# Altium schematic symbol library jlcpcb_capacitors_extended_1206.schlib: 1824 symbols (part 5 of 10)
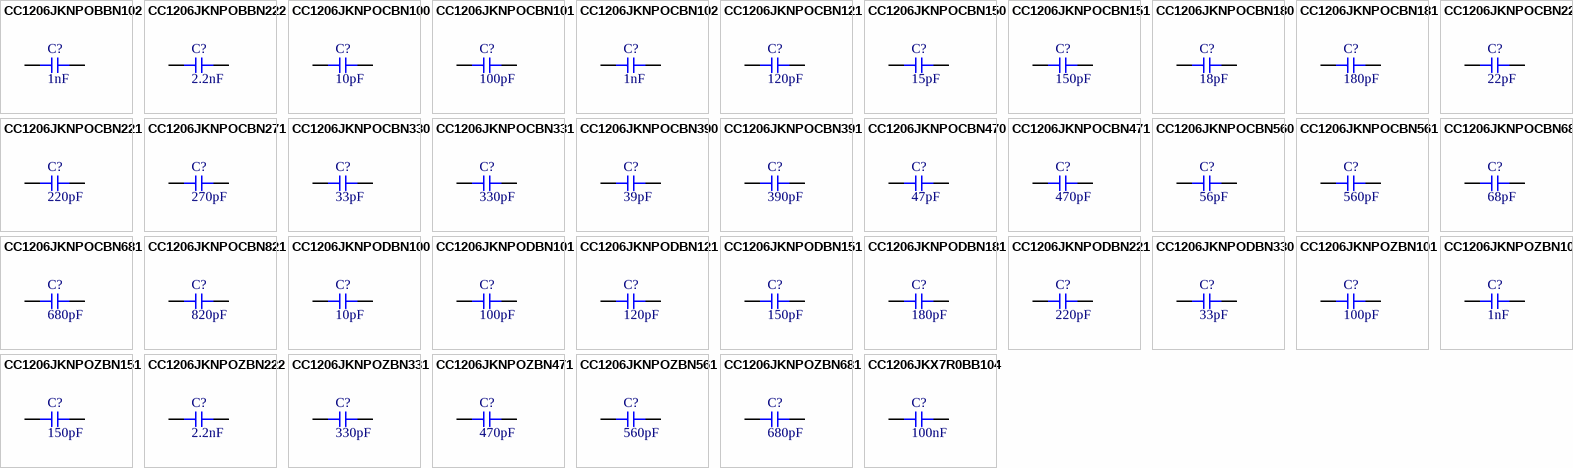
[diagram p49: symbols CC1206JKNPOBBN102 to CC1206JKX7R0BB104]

## CC1206JKNPOBBN102
designator C?  Capacitance: 1nF  (hidden comment: *)
Capacitor, Ceramic (MLCC), 1nF, ±5%, 500V, NP0, ±5%, SMD 1206; Manufacturer: YAGEO; Manufacturer Part Number: CC1206JKNPOBBN102
footprint CAP-1206 (1206 (3216M) Capacitor)
pins: 1, 2

## CC1206JKNPOBBN222
designator C?  Capacitance: 2.2nF  (hidden comment: *)
Capacitor, Ceramic (MLCC), 2.2nF, ±5%, 500V, NP0, ±5%, SMD 1206; Manufacturer: YAGEO; Manufacturer Part Number: CC1206JKNPOBBN222
footprint CAP-1206 (1206 (3216M) Capacitor)
pins: 1, 2

## CC1206JKNPOCBN100
designator C?  Capacitance: 10pF  (hidden comment: *)
Capacitor, Ceramic (MLCC), 10pF, ±5%, 1kV, NP0, ±5%, SMD 1206; Manufacturer: YAGEO; Manufacturer Part Number: CC1206JKNPOCBN100
footprint CAP-1206 (1206 (3216M) Capacitor)
pins: 1, 2

## CC1206JKNPOCBN101
designator C?  Capacitance: 100pF  (hidden comment: *)
Capacitor, Ceramic (MLCC), 100pF, ±5%, 1kV, NP0, ±5%, SMD 1206; Manufacturer: YAGEO; Manufacturer Part Number: CC1206JKNPOCBN101
footprint CAP-1206 (1206 (3216M) Capacitor)
pins: 1, 2

## CC1206JKNPOCBN102
designator C?  Capacitance: 1nF  (hidden comment: *)
Capacitor, Ceramic (MLCC), 1nF, ±5%, 1kV, NP0, ±5%, SMD 1206; Manufacturer: YAGEO; Manufacturer Part Number: CC1206JKNPOCBN102
footprint CAP-1206 (1206 (3216M) Capacitor)
pins: 1, 2

## CC1206JKNPOCBN121
designator C?  Capacitance: 120pF  (hidden comment: *)
Capacitor, Ceramic (MLCC), 120pF, ±5%, 1kV, NP0, ±5%, SMD 1206; Manufacturer: YAGEO; Manufacturer Part Number: CC1206JKNPOCBN121
footprint CAP-1206 (1206 (3216M) Capacitor)
pins: 1, 2

## CC1206JKNPOCBN150
designator C?  Capacitance: 15pF  (hidden comment: *)
Capacitor, Ceramic (MLCC), 15pF, ±5%, 1kV, NP0, ±5%, SMD 1206; Manufacturer: YAGEO; Manufacturer Part Number: CC1206JKNPOCBN150
footprint CAP-1206 (1206 (3216M) Capacitor)
pins: 1, 2

## CC1206JKNPOCBN151
designator C?  Capacitance: 150pF  (hidden comment: *)
Capacitor, Ceramic (MLCC), 150pF, ±5%, 1kV, NP0, ±5%, SMD 1206; Manufacturer: YAGEO; Manufacturer Part Number: CC1206JKNPOCBN151
footprint CAP-1206 (1206 (3216M) Capacitor)
pins: 1, 2

## CC1206JKNPOCBN180
designator C?  Capacitance: 18pF  (hidden comment: *)
Capacitor, Ceramic (MLCC), 18pF, ±5%, 1kV, NP0, ±5%, SMD 1206; Manufacturer: YAGEO; Manufacturer Part Number: CC1206JKNPOCBN180
footprint CAP-1206 (1206 (3216M) Capacitor)
pins: 1, 2

## CC1206JKNPOCBN181
designator C?  Capacitance: 180pF  (hidden comment: *)
Capacitor, Ceramic (MLCC), 180pF, ±5%, 1kV, NP0, ±5%, SMD 1206; Manufacturer: YAGEO; Manufacturer Part Number: CC1206JKNPOCBN181
footprint CAP-1206 (1206 (3216M) Capacitor)
pins: 1, 2

## CC1206JKNPOCBN220
designator C?  Capacitance: 22pF  (hidden comment: *)
Capacitor, Ceramic (MLCC), 22pF, ±5%, 1kV, NP0, ±5%, SMD 1206; Manufacturer: YAGEO; Manufacturer Part Number: CC1206JKNPOCBN220
footprint CAP-1206 (1206 (3216M) Capacitor)
pins: 1, 2

## CC1206JKNPOCBN221
designator C?  Capacitance: 220pF  (hidden comment: *)
Capacitor, Ceramic (MLCC), 220pF, ±5%, 1kV, NP0, ±5%, SMD 1206; Manufacturer: YAGEO; Manufacturer Part Number: CC1206JKNPOCBN221
footprint CAP-1206 (1206 (3216M) Capacitor)
pins: 1, 2

## CC1206JKNPOCBN271
designator C?  Capacitance: 270pF  (hidden comment: *)
Capacitor, Ceramic (MLCC), 270pF, ±5%, 1kV, NP0, ±5%, SMD 1206; Manufacturer: YAGEO; Manufacturer Part Number: CC1206JKNPOCBN271
footprint CAP-1206 (1206 (3216M) Capacitor)
pins: 1, 2

## CC1206JKNPOCBN330
designator C?  Capacitance: 33pF  (hidden comment: *)
Capacitor, Ceramic (MLCC), 33pF, ±5%, 1kV, NP0, ±5%, SMD 1206; Manufacturer: YAGEO; Manufacturer Part Number: CC1206JKNPOCBN330
footprint CAP-1206 (1206 (3216M) Capacitor)
pins: 1, 2

## CC1206JKNPOCBN331
designator C?  Capacitance: 330pF  (hidden comment: *)
Capacitor, Ceramic (MLCC), 330pF, ±5%, 1kV, NP0, ±5%, SMD 1206; Manufacturer: YAGEO; Manufacturer Part Number: CC1206JKNPOCBN331
footprint CAP-1206 (1206 (3216M) Capacitor)
pins: 1, 2

## CC1206JKNPOCBN390
designator C?  Capacitance: 39pF  (hidden comment: *)
Capacitor, Ceramic (MLCC), 39pF, ±5%, 1kV, NP0, ±5%, SMD 1206; Manufacturer: YAGEO; Manufacturer Part Number: CC1206JKNPOCBN390
footprint CAP-1206 (1206 (3216M) Capacitor)
pins: 1, 2

## CC1206JKNPOCBN391
designator C?  Capacitance: 390pF  (hidden comment: *)
Capacitor, Ceramic (MLCC), 390pF, ±5%, 1kV, NP0, ±5%, SMD 1206; Manufacturer: YAGEO; Manufacturer Part Number: CC1206JKNPOCBN391
footprint CAP-1206 (1206 (3216M) Capacitor)
pins: 1, 2

## CC1206JKNPOCBN470
designator C?  Capacitance: 47pF  (hidden comment: *)
Capacitor, Ceramic (MLCC), 47pF, ±5%, 1kV, NP0, ±5%, SMD 1206; Manufacturer: YAGEO; Manufacturer Part Number: CC1206JKNPOCBN470
footprint CAP-1206 (1206 (3216M) Capacitor)
pins: 1, 2

## CC1206JKNPOCBN471
designator C?  Capacitance: 470pF  (hidden comment: *)
Capacitor, Ceramic (MLCC), 470pF, ±5%, 1kV, NP0, ±5%, SMD 1206; Manufacturer: YAGEO; Manufacturer Part Number: CC1206JKNPOCBN471
footprint CAP-1206 (1206 (3216M) Capacitor)
pins: 1, 2

## CC1206JKNPOCBN560
designator C?  Capacitance: 56pF  (hidden comment: *)
Capacitor, Ceramic (MLCC), 56pF, ±5%, 1kV, NP0, ±5%, SMD 1206; Manufacturer: YAGEO; Manufacturer Part Number: CC1206JKNPOCBN560
footprint CAP-1206 (1206 (3216M) Capacitor)
pins: 1, 2

## CC1206JKNPOCBN561
designator C?  Capacitance: 560pF  (hidden comment: *)
Capacitor, Ceramic (MLCC), 560pF, ±5%, 1kV, NP0, ±5%, SMD 1206; Manufacturer: YAGEO; Manufacturer Part Number: CC1206JKNPOCBN561
footprint CAP-1206 (1206 (3216M) Capacitor)
pins: 1, 2

## CC1206JKNPOCBN680
designator C?  Capacitance: 68pF  (hidden comment: *)
Capacitor, Ceramic (MLCC), 68pF, ±5%, 1kV, NP0, ±5%, SMD 1206; Manufacturer: YAGEO; Manufacturer Part Number: CC1206JKNPOCBN680
footprint CAP-1206 (1206 (3216M) Capacitor)
pins: 1, 2

## CC1206JKNPOCBN681
designator C?  Capacitance: 680pF  (hidden comment: *)
Capacitor, Ceramic (MLCC), 680pF, ±5%, 1kV, NP0, ±5%, SMD 1206; Manufacturer: YAGEO; Manufacturer Part Number: CC1206JKNPOCBN681
footprint CAP-1206 (1206 (3216M) Capacitor)
pins: 1, 2

## CC1206JKNPOCBN821
designator C?  Capacitance: 820pF  (hidden comment: *)
Capacitor, Ceramic (MLCC), 820pF, ±5%, 1kV, NP0, ±5%, SMD 1206; Manufacturer: YAGEO; Manufacturer Part Number: CC1206JKNPOCBN821
footprint CAP-1206 (1206 (3216M) Capacitor)
pins: 1, 2

## CC1206JKNPODBN100
designator C?  Capacitance: 10pF  (hidden comment: *)
Capacitor, Ceramic (MLCC), 10pF, ±5%, 2kV, NP0, ±5%, SMD 1206; Manufacturer: YAGEO; Manufacturer Part Number: CC1206JKNPODBN100
footprint CAP-1206 (1206 (3216M) Capacitor)
pins: 1, 2

## CC1206JKNPODBN101
designator C?  Capacitance: 100pF  (hidden comment: *)
Capacitor, Ceramic (MLCC), 100pF, ±5%, 2kV, NP0, ±5%, SMD 1206; Manufacturer: YAGEO; Manufacturer Part Number: CC1206JKNPODBN101
footprint CAP-1206 (1206 (3216M) Capacitor)
pins: 1, 2

## CC1206JKNPODBN121
designator C?  Capacitance: 120pF  (hidden comment: *)
Capacitor, Ceramic (MLCC), 120pF, ±5%, 2kV, NP0, ±5%, SMD 1206; Manufacturer: YAGEO; Manufacturer Part Number: CC1206JKNPODBN121
footprint CAP-1206 (1206 (3216M) Capacitor)
pins: 1, 2

## CC1206JKNPODBN151
designator C?  Capacitance: 150pF  (hidden comment: *)
Capacitor, Ceramic (MLCC), 150pF, ±5%, 2kV, NP0, ±5%, SMD 1206; Manufacturer: YAGEO; Manufacturer Part Number: CC1206JKNPODBN151
footprint CAP-1206 (1206 (3216M) Capacitor)
pins: 1, 2

## CC1206JKNPODBN181
designator C?  Capacitance: 180pF  (hidden comment: *)
Capacitor, Ceramic (MLCC), 180pF, ±5%, 2kV, NP0, ±5%, SMD 1206; Manufacturer: YAGEO; Manufacturer Part Number: CC1206JKNPODBN181
footprint CAP-1206 (1206 (3216M) Capacitor)
pins: 1, 2

## CC1206JKNPODBN221
designator C?  Capacitance: 220pF  (hidden comment: *)
Capacitor, Ceramic (MLCC), 220pF, ±5%, 2kV, NP0, ±5%, SMD 1206; Manufacturer: YAGEO; Manufacturer Part Number: CC1206JKNPODBN221
footprint CAP-1206 (1206 (3216M) Capacitor)
pins: 1, 2

## CC1206JKNPODBN330
designator C?  Capacitance: 33pF  (hidden comment: *)
Capacitor, Ceramic (MLCC), 33pF, ±5%, 2kV, NP0, ±5%, SMD 1206; Manufacturer: YAGEO; Manufacturer Part Number: CC1206JKNPODBN330
footprint CAP-1206 (1206 (3216M) Capacitor)
pins: 1, 2

## CC1206JKNPOZBN101
designator C?  Capacitance: 100pF  (hidden comment: *)
Capacitor, Ceramic (MLCC), 100pF, ±5%, 630V, NP0, ±5%, SMD 1206; Manufacturer: YAGEO; Manufacturer Part Number: CC1206JKNPOZBN101
footprint CAP-1206 (1206 (3216M) Capacitor)
pins: 1, 2

## CC1206JKNPOZBN102
designator C?  Capacitance: 1nF  (hidden comment: *)
Capacitor, Ceramic (MLCC), 1nF, ±5%, 630V, NP0, ±5%, SMD 1206; Manufacturer: YAGEO; Manufacturer Part Number: CC1206JKNPOZBN102
footprint CAP-1206 (1206 (3216M) Capacitor)
pins: 1, 2

## CC1206JKNPOZBN151
designator C?  Capacitance: 150pF  (hidden comment: *)
Capacitor, Ceramic (MLCC), 150pF, ±5%, 630V, NP0, ±5%, SMD 1206; Manufacturer: YAGEO; Manufacturer Part Number: CC1206JKNPOZBN151
footprint CAP-1206 (1206 (3216M) Capacitor)
pins: 1, 2

## CC1206JKNPOZBN222
designator C?  Capacitance: 2.2nF  (hidden comment: *)
Capacitor, Ceramic (MLCC), 2.2nF, ±5%, 630V, NP0, ±5%, SMD 1206; Manufacturer: YAGEO; Manufacturer Part Number: CC1206JKNPOZBN222
footprint CAP-1206 (1206 (3216M) Capacitor)
pins: 1, 2

## CC1206JKNPOZBN331
designator C?  Capacitance: 330pF  (hidden comment: *)
Capacitor, Ceramic (MLCC), 330pF, ±5%, 630V, NP0, ±5%, SMD 1206; Manufacturer: YAGEO; Manufacturer Part Number: CC1206JKNPOZBN331
footprint CAP-1206 (1206 (3216M) Capacitor)
pins: 1, 2

## CC1206JKNPOZBN471
designator C?  Capacitance: 470pF  (hidden comment: *)
Capacitor, Ceramic (MLCC), 470pF, ±5%, 630V, NP0, ±5%, SMD 1206; Manufacturer: YAGEO; Manufacturer Part Number: CC1206JKNPOZBN471
footprint CAP-1206 (1206 (3216M) Capacitor)
pins: 1, 2

## CC1206JKNPOZBN561
designator C?  Capacitance: 560pF  (hidden comment: *)
Capacitor, Ceramic (MLCC), 560pF, ±5%, 630V, NP0, ±5%, SMD 1206; Manufacturer: YAGEO; Manufacturer Part Number: CC1206JKNPOZBN561
footprint CAP-1206 (1206 (3216M) Capacitor)
pins: 1, 2

## CC1206JKNPOZBN681
designator C?  Capacitance: 680pF  (hidden comment: *)
Capacitor, Ceramic (MLCC), 680pF, ±5%, 630V, NP0, ±5%, SMD 1206; Manufacturer: YAGEO; Manufacturer Part Number: CC1206JKNPOZBN681
footprint CAP-1206 (1206 (3216M) Capacitor)
pins: 1, 2

## CC1206JKX7R0BB104
designator C?  Capacitance: 100nF  (hidden comment: *)
Capacitor, Ceramic (MLCC), 100nF, ±5%, 100V, X7R, ±5%, SMD 1206; Manufacturer: YAGEO; Manufacturer Part Number: CC1206JKX7R0BB104
footprint CAP-1206 (1206 (3216M) Capacitor)
pins: 1, 2

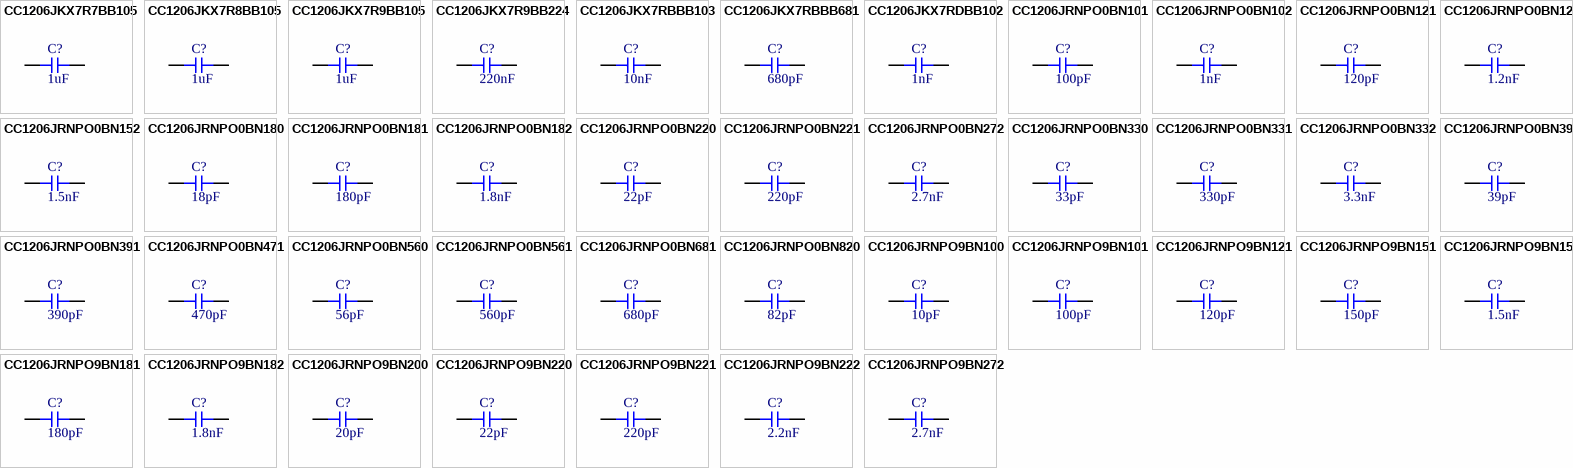
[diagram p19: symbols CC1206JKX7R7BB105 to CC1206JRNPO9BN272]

## CC1206JKX7R7BB105
designator C?  Capacitance: 1uF  (hidden comment: *)
Capacitor, Ceramic (MLCC), 1uF, ±5%, 16V, X7R, ±5%, SMD 1206; Manufacturer: YAGEO; Manufacturer Part Number: CC1206JKX7R7BB105
footprint CAP-1206 (1206 (3216M) Capacitor)
pins: 1, 2

## CC1206JKX7R8BB105
designator C?  Capacitance: 1uF  (hidden comment: *)
Capacitor, Ceramic (MLCC), 1uF, ±5%, 25V, X7R, ±5%, SMD 1206; Manufacturer: YAGEO; Manufacturer Part Number: CC1206JKX7R8BB105
footprint CAP-1206 (1206 (3216M) Capacitor)
pins: 1, 2

## CC1206JKX7R9BB105
designator C?  Capacitance: 1uF  (hidden comment: *)
Capacitor, Ceramic (MLCC), 1uF, ±5%, 50V, X7R, ±5%, SMD 1206; Manufacturer: YAGEO; Manufacturer Part Number: CC1206JKX7R9BB105
footprint CAP-1206 (1206 (3216M) Capacitor)
pins: 1, 2

## CC1206JKX7R9BB224
designator C?  Capacitance: 220nF  (hidden comment: *)
Capacitor, Ceramic (MLCC), 220nF, ±5%, 50V, X7R, ±5%, SMD 1206; Manufacturer: YAGEO; Manufacturer Part Number: CC1206JKX7R9BB224
footprint CAP-1206 (1206 (3216M) Capacitor)
pins: 1, 2

## CC1206JKX7RBBB103
designator C?  Capacitance: 10nF  (hidden comment: *)
Capacitor, Ceramic (MLCC), 10nF, ±5%, 500V, X7R, ±5%, SMD 1206; Manufacturer: YAGEO; Manufacturer Part Number: CC1206JKX7RBBB103
footprint CAP-1206 (1206 (3216M) Capacitor)
pins: 1, 2

## CC1206JKX7RBBB681
designator C?  Capacitance: 680pF  (hidden comment: *)
Capacitor, Ceramic (MLCC), 680pF, ±5%, 500V, X7R, ±5%, SMD 1206; Manufacturer: YAGEO; Manufacturer Part Number: CC1206JKX7RBBB681
footprint CAP-1206 (1206 (3216M) Capacitor)
pins: 1, 2

## CC1206JKX7RDBB102
designator C?  Capacitance: 1nF  (hidden comment: *)
Capacitor, Ceramic (MLCC), 1nF, ±5%, 2kV, X7R, ±5%, SMD 1206; Manufacturer: YAGEO; Manufacturer Part Number: CC1206JKX7RDBB102
footprint CAP-1206 (1206 (3216M) Capacitor)
pins: 1, 2

## CC1206JRNPO0BN101
designator C?  Capacitance: 100pF  (hidden comment: *)
Capacitor, Ceramic (MLCC), 100pF, ±5%, 100V, NP0, ±5%, SMD 1206; Manufacturer: YAGEO; Manufacturer Part Number: CC1206JRNPO0BN101
footprint CAP-1206 (1206 (3216M) Capacitor)
pins: 1, 2

## CC1206JRNPO0BN102
designator C?  Capacitance: 1nF  (hidden comment: *)
Capacitor, Ceramic (MLCC), 1nF, ±5%, 100V, NP0, ±5%, SMD 1206; Manufacturer: YAGEO; Manufacturer Part Number: CC1206JRNPO0BN102
footprint CAP-1206 (1206 (3216M) Capacitor)
pins: 1, 2

## CC1206JRNPO0BN121
designator C?  Capacitance: 120pF  (hidden comment: *)
Capacitor, Ceramic (MLCC), 120pF, ±5%, 100V, NP0, ±5%, SMD 1206; Manufacturer: YAGEO; Manufacturer Part Number: CC1206JRNPO0BN121
footprint CAP-1206 (1206 (3216M) Capacitor)
pins: 1, 2

## CC1206JRNPO0BN122
designator C?  Capacitance: 1.2nF  (hidden comment: *)
Capacitor, Ceramic (MLCC), 1.2nF, ±5%, 100V, NP0, ±5%, SMD 1206; Manufacturer: YAGEO; Manufacturer Part Number: CC1206JRNPO0BN122
footprint CAP-1206 (1206 (3216M) Capacitor)
pins: 1, 2

## CC1206JRNPO0BN152
designator C?  Capacitance: 1.5nF  (hidden comment: *)
Capacitor, Ceramic (MLCC), 1.5nF, ±5%, 100V, NP0, ±5%, SMD 1206; Manufacturer: YAGEO; Manufacturer Part Number: CC1206JRNPO0BN152
footprint CAP-1206 (1206 (3216M) Capacitor)
pins: 1, 2

## CC1206JRNPO0BN180
designator C?  Capacitance: 18pF  (hidden comment: *)
Capacitor, Ceramic (MLCC), 18pF, ±5%, 100V, NP0, ±5%, SMD 1206; Manufacturer: YAGEO; Manufacturer Part Number: CC1206JRNPO0BN180
footprint CAP-1206 (1206 (3216M) Capacitor)
pins: 1, 2

## CC1206JRNPO0BN181
designator C?  Capacitance: 180pF  (hidden comment: *)
Capacitor, Ceramic (MLCC), 180pF, ±5%, 100V, NP0, ±5%, SMD 1206; Manufacturer: YAGEO; Manufacturer Part Number: CC1206JRNPO0BN181
footprint CAP-1206 (1206 (3216M) Capacitor)
pins: 1, 2

## CC1206JRNPO0BN182
designator C?  Capacitance: 1.8nF  (hidden comment: *)
Capacitor, Ceramic (MLCC), 1.8nF, ±5%, 100V, NP0, ±5%, SMD 1206; Manufacturer: YAGEO; Manufacturer Part Number: CC1206JRNPO0BN182
footprint CAP-1206 (1206 (3216M) Capacitor)
pins: 1, 2

## CC1206JRNPO0BN220
designator C?  Capacitance: 22pF  (hidden comment: *)
Capacitor, Ceramic (MLCC), 22pF, ±5%, 100V, NP0, ±5%, SMD 1206; Manufacturer: YAGEO; Manufacturer Part Number: CC1206JRNPO0BN220
footprint CAP-1206 (1206 (3216M) Capacitor)
pins: 1, 2

## CC1206JRNPO0BN221
designator C?  Capacitance: 220pF  (hidden comment: *)
Capacitor, Ceramic (MLCC), 220pF, ±5%, 100V, NP0, ±5%, SMD 1206; Manufacturer: YAGEO; Manufacturer Part Number: CC1206JRNPO0BN221
footprint CAP-1206 (1206 (3216M) Capacitor)
pins: 1, 2

## CC1206JRNPO0BN272
designator C?  Capacitance: 2.7nF  (hidden comment: *)
Capacitor, Ceramic (MLCC), 2.7nF, ±5%, 100V, NP0, ±5%, SMD 1206; Manufacturer: YAGEO; Manufacturer Part Number: CC1206JRNPO0BN272
footprint CAP-1206 (1206 (3216M) Capacitor)
pins: 1, 2

## CC1206JRNPO0BN330
designator C?  Capacitance: 33pF  (hidden comment: *)
Capacitor, Ceramic (MLCC), 33pF, ±5%, 100V, NP0, ±5%, SMD 1206; Manufacturer: YAGEO; Manufacturer Part Number: CC1206JRNPO0BN330
footprint CAP-1206 (1206 (3216M) Capacitor)
pins: 1, 2

## CC1206JRNPO0BN331
designator C?  Capacitance: 330pF  (hidden comment: *)
Capacitor, Ceramic (MLCC), 330pF, ±5%, 100V, NP0, ±5%, SMD 1206; Manufacturer: YAGEO; Manufacturer Part Number: CC1206JRNPO0BN331
footprint CAP-1206 (1206 (3216M) Capacitor)
pins: 1, 2

## CC1206JRNPO0BN332
designator C?  Capacitance: 3.3nF  (hidden comment: *)
Capacitor, Ceramic (MLCC), 3.3nF, ±5%, 100V, NP0, ±5%, SMD 1206; Manufacturer: YAGEO; Manufacturer Part Number: CC1206JRNPO0BN332
footprint CAP-1206 (1206 (3216M) Capacitor)
pins: 1, 2

## CC1206JRNPO0BN390
designator C?  Capacitance: 39pF  (hidden comment: *)
Capacitor, Ceramic (MLCC), 39pF, ±5%, 100V, NP0, ±5%, SMD 1206; Manufacturer: YAGEO; Manufacturer Part Number: CC1206JRNPO0BN390
footprint CAP-1206 (1206 (3216M) Capacitor)
pins: 1, 2

## CC1206JRNPO0BN391
designator C?  Capacitance: 390pF  (hidden comment: *)
Capacitor, Ceramic (MLCC), 390pF, ±5%, 100V, NP0, ±5%, SMD 1206; Manufacturer: YAGEO; Manufacturer Part Number: CC1206JRNPO0BN391
footprint CAP-1206 (1206 (3216M) Capacitor)
pins: 1, 2

## CC1206JRNPO0BN471
designator C?  Capacitance: 470pF  (hidden comment: *)
Capacitor, Ceramic (MLCC), 470pF, ±5%, 100V, NP0, ±5%, SMD 1206; Manufacturer: YAGEO; Manufacturer Part Number: CC1206JRNPO0BN471
footprint CAP-1206 (1206 (3216M) Capacitor)
pins: 1, 2

## CC1206JRNPO0BN560
designator C?  Capacitance: 56pF  (hidden comment: *)
Capacitor, Ceramic (MLCC), 56pF, ±5%, 100V, NP0, ±5%, SMD 1206; Manufacturer: YAGEO; Manufacturer Part Number: CC1206JRNPO0BN560
footprint CAP-1206 (1206 (3216M) Capacitor)
pins: 1, 2

## CC1206JRNPO0BN561
designator C?  Capacitance: 560pF  (hidden comment: *)
Capacitor, Ceramic (MLCC), 560pF, ±5%, 100V, NP0, ±5%, SMD 1206; Manufacturer: YAGEO; Manufacturer Part Number: CC1206JRNPO0BN561
footprint CAP-1206 (1206 (3216M) Capacitor)
pins: 1, 2

## CC1206JRNPO0BN681
designator C?  Capacitance: 680pF  (hidden comment: *)
Capacitor, Ceramic (MLCC), 680pF, ±5%, 100V, NP0, ±5%, SMD 1206; Manufacturer: YAGEO; Manufacturer Part Number: CC1206JRNPO0BN681
footprint CAP-1206 (1206 (3216M) Capacitor)
pins: 1, 2

## CC1206JRNPO0BN820
designator C?  Capacitance: 82pF  (hidden comment: *)
Capacitor, Ceramic (MLCC), 82pF, ±5%, 100V, NP0, ±5%, SMD 1206; Manufacturer: YAGEO; Manufacturer Part Number: CC1206JRNPO0BN820
footprint CAP-1206 (1206 (3216M) Capacitor)
pins: 1, 2

## CC1206JRNPO9BN100
designator C?  Capacitance: 10pF  (hidden comment: *)
Capacitor, Ceramic (MLCC), 10pF, ±5%, 50V, NP0, ±5%, SMD 1206; Manufacturer: YAGEO; Manufacturer Part Number: CC1206JRNPO9BN100
footprint CAP-1206 (1206 (3216M) Capacitor)
pins: 1, 2

## CC1206JRNPO9BN101
designator C?  Capacitance: 100pF  (hidden comment: *)
Capacitor, Ceramic (MLCC), 100pF, ±5%, 50V, NP0, ±5%, SMD 1206; Manufacturer: YAGEO; Manufacturer Part Number: CC1206JRNPO9BN101
footprint CAP-1206 (1206 (3216M) Capacitor)
pins: 1, 2

## CC1206JRNPO9BN121
designator C?  Capacitance: 120pF  (hidden comment: *)
Capacitor, Ceramic (MLCC), 120pF, ±5%, 50V, NP0, ±5%, SMD 1206; Manufacturer: YAGEO; Manufacturer Part Number: CC1206JRNPO9BN121
footprint CAP-1206 (1206 (3216M) Capacitor)
pins: 1, 2

## CC1206JRNPO9BN151
designator C?  Capacitance: 150pF  (hidden comment: *)
Capacitor, Ceramic (MLCC), 150pF, ±5%, 50V, NP0, ±5%, SMD 1206; Manufacturer: YAGEO; Manufacturer Part Number: CC1206JRNPO9BN151
footprint CAP-1206 (1206 (3216M) Capacitor)
pins: 1, 2

## CC1206JRNPO9BN152
designator C?  Capacitance: 1.5nF  (hidden comment: *)
Capacitor, Ceramic (MLCC), 1.5nF, ±5%, 50V, NP0, ±5%, SMD 1206; Manufacturer: YAGEO; Manufacturer Part Number: CC1206JRNPO9BN152
footprint CAP-1206 (1206 (3216M) Capacitor)
pins: 1, 2

## CC1206JRNPO9BN181
designator C?  Capacitance: 180pF  (hidden comment: *)
Capacitor, Ceramic (MLCC), 180pF, ±5%, 50V, NP0, ±5%, SMD 1206; Manufacturer: YAGEO; Manufacturer Part Number: CC1206JRNPO9BN181
footprint CAP-1206 (1206 (3216M) Capacitor)
pins: 1, 2

## CC1206JRNPO9BN182
designator C?  Capacitance: 1.8nF  (hidden comment: *)
Capacitor, Ceramic (MLCC), 1.8nF, ±5%, 50V, NP0, ±5%, SMD 1206; Manufacturer: YAGEO; Manufacturer Part Number: CC1206JRNPO9BN182
footprint CAP-1206 (1206 (3216M) Capacitor)
pins: 1, 2

## CC1206JRNPO9BN200
designator C?  Capacitance: 20pF  (hidden comment: *)
Capacitor, Ceramic (MLCC), 20pF, ±5%, 50V, NP0, ±5%, SMD 1206; Manufacturer: YAGEO; Manufacturer Part Number: CC1206JRNPO9BN200
footprint CAP-1206 (1206 (3216M) Capacitor)
pins: 1, 2

## CC1206JRNPO9BN220
designator C?  Capacitance: 22pF  (hidden comment: *)
Capacitor, Ceramic (MLCC), 22pF, ±5%, 50V, NP0, ±5%, SMD 1206; Manufacturer: YAGEO; Manufacturer Part Number: CC1206JRNPO9BN220
footprint CAP-1206 (1206 (3216M) Capacitor)
pins: 1, 2

## CC1206JRNPO9BN221
designator C?  Capacitance: 220pF  (hidden comment: *)
Capacitor, Ceramic (MLCC), 220pF, ±5%, 50V, NP0, ±5%, SMD 1206; Manufacturer: YAGEO; Manufacturer Part Number: CC1206JRNPO9BN221
footprint CAP-1206 (1206 (3216M) Capacitor)
pins: 1, 2

## CC1206JRNPO9BN222
designator C?  Capacitance: 2.2nF  (hidden comment: *)
Capacitor, Ceramic (MLCC), 2.2nF, ±5%, 50V, NP0, ±5%, SMD 1206; Manufacturer: YAGEO; Manufacturer Part Number: CC1206JRNPO9BN222
footprint CAP-1206 (1206 (3216M) Capacitor)
pins: 1, 2

## CC1206JRNPO9BN272
designator C?  Capacitance: 2.7nF  (hidden comment: *)
Capacitor, Ceramic (MLCC), 2.7nF, ±5%, 50V, NP0, ±5%, SMD 1206; Manufacturer: YAGEO; Manufacturer Part Number: CC1206JRNPO9BN272
footprint CAP-1206 (1206 (3216M) Capacitor)
pins: 1, 2

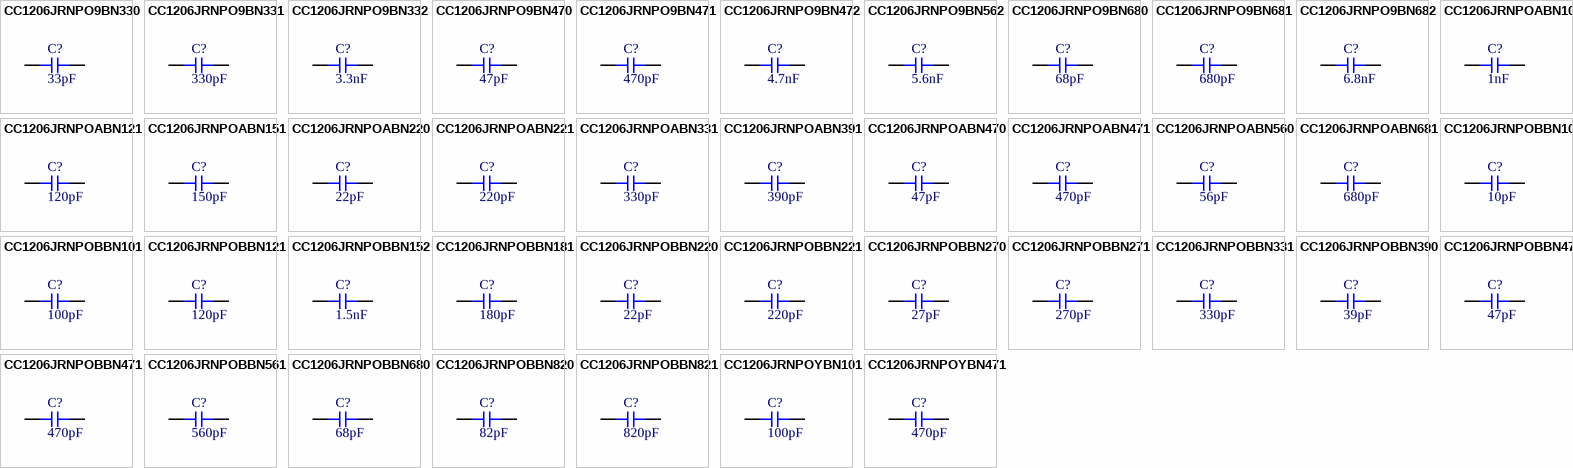
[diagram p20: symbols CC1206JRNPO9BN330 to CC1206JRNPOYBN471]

## CC1206JRNPO9BN330
designator C?  Capacitance: 33pF  (hidden comment: *)
Capacitor, Ceramic (MLCC), 33pF, ±5%, 50V, NP0, ±5%, SMD 1206; Manufacturer: YAGEO; Manufacturer Part Number: CC1206JRNPO9BN330
footprint CAP-1206 (1206 (3216M) Capacitor)
pins: 1, 2

## CC1206JRNPO9BN331
designator C?  Capacitance: 330pF  (hidden comment: *)
Capacitor, Ceramic (MLCC), 330pF, ±5%, 50V, NP0, ±5%, SMD 1206; Manufacturer: YAGEO; Manufacturer Part Number: CC1206JRNPO9BN331
footprint CAP-1206 (1206 (3216M) Capacitor)
pins: 1, 2

## CC1206JRNPO9BN332
designator C?  Capacitance: 3.3nF  (hidden comment: *)
Capacitor, Ceramic (MLCC), 3.3nF, ±5%, 50V, NP0, ±5%, SMD 1206; Manufacturer: YAGEO; Manufacturer Part Number: CC1206JRNPO9BN332
footprint CAP-1206 (1206 (3216M) Capacitor)
pins: 1, 2

## CC1206JRNPO9BN470
designator C?  Capacitance: 47pF  (hidden comment: *)
Capacitor, Ceramic (MLCC), 47pF, ±5%, 50V, NP0, ±5%, SMD 1206; Manufacturer: YAGEO; Manufacturer Part Number: CC1206JRNPO9BN470
footprint CAP-1206 (1206 (3216M) Capacitor)
pins: 1, 2

## CC1206JRNPO9BN471
designator C?  Capacitance: 470pF  (hidden comment: *)
Capacitor, Ceramic (MLCC), 470pF, ±5%, 50V, NP0, ±5%, SMD 1206; Manufacturer: YAGEO; Manufacturer Part Number: CC1206JRNPO9BN471
footprint CAP-1206 (1206 (3216M) Capacitor)
pins: 1, 2

## CC1206JRNPO9BN472
designator C?  Capacitance: 4.7nF  (hidden comment: *)
Capacitor, Ceramic (MLCC), 4.7nF, ±5%, 50V, NP0, ±5%, SMD 1206; Manufacturer: YAGEO; Manufacturer Part Number: CC1206JRNPO9BN472
footprint CAP-1206 (1206 (3216M) Capacitor)
pins: 1, 2

## CC1206JRNPO9BN562
designator C?  Capacitance: 5.6nF  (hidden comment: *)
Capacitor, Ceramic (MLCC), 5.6nF, ±5%, 50V, NP0, ±5%, SMD 1206; Manufacturer: YAGEO; Manufacturer Part Number: CC1206JRNPO9BN562
footprint CAP-1206 (1206 (3216M) Capacitor)
pins: 1, 2

## CC1206JRNPO9BN680
designator C?  Capacitance: 68pF  (hidden comment: *)
Capacitor, Ceramic (MLCC), 68pF, ±5%, 50V, NP0, ±5%, SMD 1206; Manufacturer: YAGEO; Manufacturer Part Number: CC1206JRNPO9BN680
footprint CAP-1206 (1206 (3216M) Capacitor)
pins: 1, 2

## CC1206JRNPO9BN681
designator C?  Capacitance: 680pF  (hidden comment: *)
Capacitor, Ceramic (MLCC), 680pF, ±5%, 50V, NP0, ±5%, SMD 1206; Manufacturer: YAGEO; Manufacturer Part Number: CC1206JRNPO9BN681
footprint CAP-1206 (1206 (3216M) Capacitor)
pins: 1, 2

## CC1206JRNPO9BN682
designator C?  Capacitance: 6.8nF  (hidden comment: *)
Capacitor, Ceramic (MLCC), 6.8nF, ±5%, 50V, NP0, ±5%, SMD 1206; Manufacturer: YAGEO; Manufacturer Part Number: CC1206JRNPO9BN682
footprint CAP-1206 (1206 (3216M) Capacitor)
pins: 1, 2

## CC1206JRNPOABN102
designator C?  Capacitance: 1nF  (hidden comment: *)
Capacitor, Ceramic (MLCC), 1nF, ±5%, 200V, NP0, ±5%, SMD 1206; Manufacturer: YAGEO; Manufacturer Part Number: CC1206JRNPOABN102
footprint CAP-1206 (1206 (3216M) Capacitor)
pins: 1, 2

## CC1206JRNPOABN121
designator C?  Capacitance: 120pF  (hidden comment: *)
Capacitor, Ceramic (MLCC), 120pF, ±5%, 200V, NP0, ±5%, SMD 1206; Manufacturer: YAGEO; Manufacturer Part Number: CC1206JRNPOABN121
footprint CAP-1206 (1206 (3216M) Capacitor)
pins: 1, 2

## CC1206JRNPOABN151
designator C?  Capacitance: 150pF  (hidden comment: *)
Capacitor, Ceramic (MLCC), 150pF, ±5%, 200V, NP0, ±5%, SMD 1206; Manufacturer: YAGEO; Manufacturer Part Number: CC1206JRNPOABN151
footprint CAP-1206 (1206 (3216M) Capacitor)
pins: 1, 2

## CC1206JRNPOABN220
designator C?  Capacitance: 22pF  (hidden comment: *)
Capacitor, Ceramic (MLCC), 22pF, ±5%, 200V, NP0, ±5%, SMD 1206; Manufacturer: YAGEO; Manufacturer Part Number: CC1206JRNPOABN220
footprint CAP-1206 (1206 (3216M) Capacitor)
pins: 1, 2

## CC1206JRNPOABN221
designator C?  Capacitance: 220pF  (hidden comment: *)
Capacitor, Ceramic (MLCC), 220pF, ±5%, 200V, NP0, ±5%, SMD 1206; Manufacturer: YAGEO; Manufacturer Part Number: CC1206JRNPOABN221
footprint CAP-1206 (1206 (3216M) Capacitor)
pins: 1, 2

## CC1206JRNPOABN331
designator C?  Capacitance: 330pF  (hidden comment: *)
Capacitor, Ceramic (MLCC), 330pF, ±5%, 200V, NP0, ±5%, SMD 1206; Manufacturer: YAGEO; Manufacturer Part Number: CC1206JRNPOABN331
footprint CAP-1206 (1206 (3216M) Capacitor)
pins: 1, 2

## CC1206JRNPOABN391
designator C?  Capacitance: 390pF  (hidden comment: *)
Capacitor, Ceramic (MLCC), 390pF, ±5%, 200V, NP0, ±5%, SMD 1206; Manufacturer: YAGEO; Manufacturer Part Number: CC1206JRNPOABN391
footprint CAP-1206 (1206 (3216M) Capacitor)
pins: 1, 2

## CC1206JRNPOABN470
designator C?  Capacitance: 47pF  (hidden comment: *)
Capacitor, Ceramic (MLCC), 47pF, ±5%, 200V, NP0, ±5%, SMD 1206; Manufacturer: YAGEO; Manufacturer Part Number: CC1206JRNPOABN470
footprint CAP-1206 (1206 (3216M) Capacitor)
pins: 1, 2

## CC1206JRNPOABN471
designator C?  Capacitance: 470pF  (hidden comment: *)
Capacitor, Ceramic (MLCC), 470pF, ±5%, 200V, NP0, ±5%, SMD 1206; Manufacturer: YAGEO; Manufacturer Part Number: CC1206JRNPOABN471
footprint CAP-1206 (1206 (3216M) Capacitor)
pins: 1, 2

## CC1206JRNPOABN560
designator C?  Capacitance: 56pF  (hidden comment: *)
Capacitor, Ceramic (MLCC), 56pF, ±5%, 200V, NP0, ±5%, SMD 1206; Manufacturer: YAGEO; Manufacturer Part Number: CC1206JRNPOABN560
footprint CAP-1206 (1206 (3216M) Capacitor)
pins: 1, 2

## CC1206JRNPOABN681
designator C?  Capacitance: 680pF  (hidden comment: *)
Capacitor, Ceramic (MLCC), 680pF, ±5%, 200V, NP0, ±5%, SMD 1206; Manufacturer: YAGEO; Manufacturer Part Number: CC1206JRNPOABN681
footprint CAP-1206 (1206 (3216M) Capacitor)
pins: 1, 2

## CC1206JRNPOBBN100
designator C?  Capacitance: 10pF  (hidden comment: *)
Capacitor, Ceramic (MLCC), 10pF, ±5%, 500V, NP0, ±5%, SMD 1206; Manufacturer: YAGEO; Manufacturer Part Number: CC1206JRNPOBBN100
footprint CAP-1206 (1206 (3216M) Capacitor)
pins: 1, 2

## CC1206JRNPOBBN101
designator C?  Capacitance: 100pF  (hidden comment: *)
Capacitor, Ceramic (MLCC), 100pF, ±5%, 500V, NP0, ±5%, SMD 1206; Manufacturer: YAGEO; Manufacturer Part Number: CC1206JRNPOBBN101
footprint CAP-1206 (1206 (3216M) Capacitor)
pins: 1, 2

## CC1206JRNPOBBN121
designator C?  Capacitance: 120pF  (hidden comment: *)
Capacitor, Ceramic (MLCC), 120pF, ±5%, 500V, NP0, ±5%, SMD 1206; Manufacturer: YAGEO; Manufacturer Part Number: CC1206JRNPOBBN121
footprint CAP-1206 (1206 (3216M) Capacitor)
pins: 1, 2

## CC1206JRNPOBBN152
designator C?  Capacitance: 1.5nF  (hidden comment: *)
Capacitor, Ceramic (MLCC), 1.5nF, ±5%, 500V, NP0, ±5%, SMD 1206; Manufacturer: YAGEO; Manufacturer Part Number: CC1206JRNPOBBN152
footprint CAP-1206 (1206 (3216M) Capacitor)
pins: 1, 2

## CC1206JRNPOBBN181
designator C?  Capacitance: 180pF  (hidden comment: *)
Capacitor, Ceramic (MLCC), 180pF, ±5%, 500V, NP0, ±5%, SMD 1206; Manufacturer: YAGEO; Manufacturer Part Number: CC1206JRNPOBBN181
footprint CAP-1206 (1206 (3216M) Capacitor)
pins: 1, 2

## CC1206JRNPOBBN220
designator C?  Capacitance: 22pF  (hidden comment: *)
Capacitor, Ceramic (MLCC), 22pF, ±5%, 500V, NP0, ±5%, SMD 1206; Manufacturer: YAGEO; Manufacturer Part Number: CC1206JRNPOBBN220
footprint CAP-1206 (1206 (3216M) Capacitor)
pins: 1, 2

## CC1206JRNPOBBN221
designator C?  Capacitance: 220pF  (hidden comment: *)
Capacitor, Ceramic (MLCC), 220pF, ±5%, 500V, NP0, ±5%, SMD 1206; Manufacturer: YAGEO; Manufacturer Part Number: CC1206JRNPOBBN221
footprint CAP-1206 (1206 (3216M) Capacitor)
pins: 1, 2

## CC1206JRNPOBBN270
designator C?  Capacitance: 27pF  (hidden comment: *)
Capacitor, Ceramic (MLCC), 27pF, ±5%, 500V, NP0, ±5%, SMD 1206; Manufacturer: YAGEO; Manufacturer Part Number: CC1206JRNPOBBN270
footprint CAP-1206 (1206 (3216M) Capacitor)
pins: 1, 2

## CC1206JRNPOBBN271
designator C?  Capacitance: 270pF  (hidden comment: *)
Capacitor, Ceramic (MLCC), 270pF, ±5%, 500V, NP0, ±5%, SMD 1206; Manufacturer: YAGEO; Manufacturer Part Number: CC1206JRNPOBBN271
footprint CAP-1206 (1206 (3216M) Capacitor)
pins: 1, 2

## CC1206JRNPOBBN331
designator C?  Capacitance: 330pF  (hidden comment: *)
Capacitor, Ceramic (MLCC), 330pF, ±5%, 500V, NP0, ±5%, SMD 1206; Manufacturer: YAGEO; Manufacturer Part Number: CC1206JRNPOBBN331
footprint CAP-1206 (1206 (3216M) Capacitor)
pins: 1, 2

## CC1206JRNPOBBN390
designator C?  Capacitance: 39pF  (hidden comment: *)
Capacitor, Ceramic (MLCC), 39pF, ±5%, 500V, NP0, ±5%, SMD 1206; Manufacturer: YAGEO; Manufacturer Part Number: CC1206JRNPOBBN390
footprint CAP-1206 (1206 (3216M) Capacitor)
pins: 1, 2

## CC1206JRNPOBBN470
designator C?  Capacitance: 47pF  (hidden comment: *)
Capacitor, Ceramic (MLCC), 47pF, ±5%, 500V, NP0, ±5%, SMD 1206; Manufacturer: YAGEO; Manufacturer Part Number: CC1206JRNPOBBN470
footprint CAP-1206 (1206 (3216M) Capacitor)
pins: 1, 2

## CC1206JRNPOBBN471
designator C?  Capacitance: 470pF  (hidden comment: *)
Capacitor, Ceramic (MLCC), 470pF, ±5%, 500V, NP0, ±5%, SMD 1206; Manufacturer: YAGEO; Manufacturer Part Number: CC1206JRNPOBBN471
footprint CAP-1206 (1206 (3216M) Capacitor)
pins: 1, 2

## CC1206JRNPOBBN561
designator C?  Capacitance: 560pF  (hidden comment: *)
Capacitor, Ceramic (MLCC), 560pF, ±5%, 500V, NP0, ±5%, SMD 1206; Manufacturer: YAGEO; Manufacturer Part Number: CC1206JRNPOBBN561
footprint CAP-1206 (1206 (3216M) Capacitor)
pins: 1, 2

## CC1206JRNPOBBN680
designator C?  Capacitance: 68pF  (hidden comment: *)
Capacitor, Ceramic (MLCC), 68pF, ±5%, 500V, NP0, ±5%, SMD 1206; Manufacturer: YAGEO; Manufacturer Part Number: CC1206JRNPOBBN680
footprint CAP-1206 (1206 (3216M) Capacitor)
pins: 1, 2

## CC1206JRNPOBBN820
designator C?  Capacitance: 82pF  (hidden comment: *)
Capacitor, Ceramic (MLCC), 82pF, ±5%, 500V, NP0, ±5%, SMD 1206; Manufacturer: YAGEO; Manufacturer Part Number: CC1206JRNPOBBN820
footprint CAP-1206 (1206 (3216M) Capacitor)
pins: 1, 2

## CC1206JRNPOBBN821
designator C?  Capacitance: 820pF  (hidden comment: *)
Capacitor, Ceramic (MLCC), 820pF, ±5%, 500V, NP0, ±5%, SMD 1206; Manufacturer: YAGEO; Manufacturer Part Number: CC1206JRNPOBBN821
footprint CAP-1206 (1206 (3216M) Capacitor)
pins: 1, 2

## CC1206JRNPOYBN101
designator C?  Capacitance: 100pF  (hidden comment: *)
Capacitor, Ceramic (MLCC), 100pF, ±5%, 250V, NP0, ±5%, SMD 1206; Manufacturer: YAGEO; Manufacturer Part Number: CC1206JRNPOYBN101
footprint CAP-1206 (1206 (3216M) Capacitor)
pins: 1, 2

## CC1206JRNPOYBN471
designator C?  Capacitance: 470pF  (hidden comment: *)
Capacitor, Ceramic (MLCC), 470pF, ±5%, 250V, NP0, ±5%, SMD 1206; Manufacturer: YAGEO; Manufacturer Part Number: CC1206JRNPOYBN471
footprint CAP-1206 (1206 (3216M) Capacitor)
pins: 1, 2

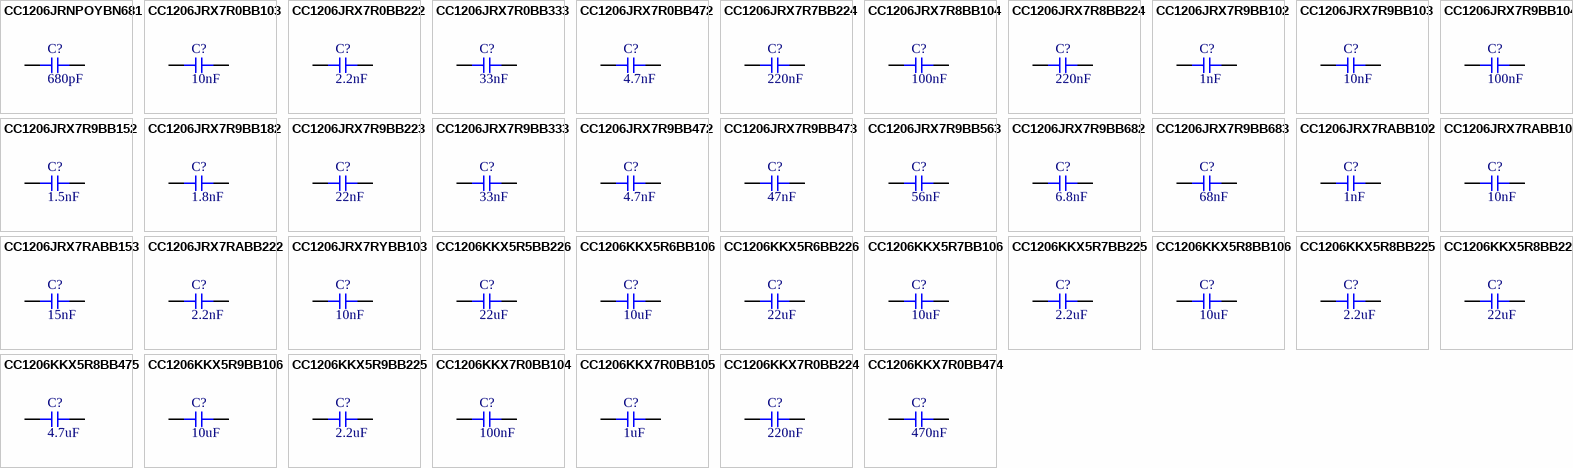
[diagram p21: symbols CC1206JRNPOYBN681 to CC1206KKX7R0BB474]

## CC1206JRNPOYBN681
designator C?  Capacitance: 680pF  (hidden comment: *)
Capacitor, Ceramic (MLCC), 680pF, ±5%, 250V, NP0, ±5%, SMD 1206; Manufacturer: YAGEO; Manufacturer Part Number: CC1206JRNPOYBN681
footprint CAP-1206 (1206 (3216M) Capacitor)
pins: 1, 2

## CC1206JRX7R0BB103
designator C?  Capacitance: 10nF  (hidden comment: *)
Capacitor, Ceramic (MLCC), 10nF, ±5%, 100V, X7R, ±5%, SMD 1206; Manufacturer: YAGEO; Manufacturer Part Number: CC1206JRX7R0BB103
footprint CAP-1206 (1206 (3216M) Capacitor)
pins: 1, 2

## CC1206JRX7R0BB222
designator C?  Capacitance: 2.2nF  (hidden comment: *)
Capacitor, Ceramic (MLCC), 2.2nF, ±5%, 100V, X7R, ±5%, SMD 1206; Manufacturer: YAGEO; Manufacturer Part Number: CC1206JRX7R0BB222
footprint CAP-1206 (1206 (3216M) Capacitor)
pins: 1, 2

## CC1206JRX7R0BB333
designator C?  Capacitance: 33nF  (hidden comment: *)
Capacitor, Ceramic (MLCC), 33nF, ±5%, 100V, X7R, ±5%, SMD 1206; Manufacturer: YAGEO; Manufacturer Part Number: CC1206JRX7R0BB333
footprint CAP-1206 (1206 (3216M) Capacitor)
pins: 1, 2

## CC1206JRX7R0BB472
designator C?  Capacitance: 4.7nF  (hidden comment: *)
Capacitor, Ceramic (MLCC), 4.7nF, ±5%, 100V, X7R, ±5%, SMD 1206; Manufacturer: YAGEO; Manufacturer Part Number: CC1206JRX7R0BB472
footprint CAP-1206 (1206 (3216M) Capacitor)
pins: 1, 2

## CC1206JRX7R7BB224
designator C?  Capacitance: 220nF  (hidden comment: *)
Capacitor, Ceramic (MLCC), 220nF, ±5%, 16V, X7R, ±5%, SMD 1206; Manufacturer: YAGEO; Manufacturer Part Number: CC1206JRX7R7BB224
footprint CAP-1206 (1206 (3216M) Capacitor)
pins: 1, 2

## CC1206JRX7R8BB104
designator C?  Capacitance: 100nF  (hidden comment: *)
Capacitor, Ceramic (MLCC), 100nF, ±5%, 25V, X7R, ±5%, SMD 1206; Manufacturer: YAGEO; Manufacturer Part Number: CC1206JRX7R8BB104
footprint CAP-1206 (1206 (3216M) Capacitor)
pins: 1, 2

## CC1206JRX7R8BB224
designator C?  Capacitance: 220nF  (hidden comment: *)
Capacitor, Ceramic (MLCC), 220nF, ±5%, 25V, X7R, ±5%, SMD 1206; Manufacturer: YAGEO; Manufacturer Part Number: CC1206JRX7R8BB224
footprint CAP-1206 (1206 (3216M) Capacitor)
pins: 1, 2

## CC1206JRX7R9BB102
designator C?  Capacitance: 1nF  (hidden comment: *)
Capacitor, Ceramic (MLCC), 1nF, ±5%, 50V, X7R, ±5%, SMD 1206; Manufacturer: YAGEO; Manufacturer Part Number: CC1206JRX7R9BB102
footprint CAP-1206 (1206 (3216M) Capacitor)
pins: 1, 2

## CC1206JRX7R9BB103
designator C?  Capacitance: 10nF  (hidden comment: *)
Capacitor, Ceramic (MLCC), 10nF, ±5%, 50V, X7R, ±5%, SMD 1206; Manufacturer: YAGEO; Manufacturer Part Number: CC1206JRX7R9BB103
footprint CAP-1206 (1206 (3216M) Capacitor)
pins: 1, 2

## CC1206JRX7R9BB104
designator C?  Capacitance: 100nF  (hidden comment: *)
Capacitor, Ceramic (MLCC), 100nF, ±5%, 50V, X7R, ±5%, SMD 1206; Manufacturer: YAGEO; Manufacturer Part Number: CC1206JRX7R9BB104
footprint CAP-1206 (1206 (3216M) Capacitor)
pins: 1, 2

## CC1206JRX7R9BB152
designator C?  Capacitance: 1.5nF  (hidden comment: *)
Capacitor, Ceramic (MLCC), 1.5nF, ±5%, 50V, X7R, ±5%, SMD 1206; Manufacturer: YAGEO; Manufacturer Part Number: CC1206JRX7R9BB152
footprint CAP-1206 (1206 (3216M) Capacitor)
pins: 1, 2

## CC1206JRX7R9BB182
designator C?  Capacitance: 1.8nF  (hidden comment: *)
Capacitor, Ceramic (MLCC), 1.8nF, ±5%, 50V, X7R, ±5%, SMD 1206; Manufacturer: YAGEO; Manufacturer Part Number: CC1206JRX7R9BB182
footprint CAP-1206 (1206 (3216M) Capacitor)
pins: 1, 2

## CC1206JRX7R9BB223
designator C?  Capacitance: 22nF  (hidden comment: *)
Capacitor, Ceramic (MLCC), 22nF, ±5%, 50V, X7R, ±5%, SMD 1206; Manufacturer: YAGEO; Manufacturer Part Number: CC1206JRX7R9BB223
footprint CAP-1206 (1206 (3216M) Capacitor)
pins: 1, 2

## CC1206JRX7R9BB333
designator C?  Capacitance: 33nF  (hidden comment: *)
Capacitor, Ceramic (MLCC), 33nF, ±5%, 50V, X7R, ±5%, SMD 1206; Manufacturer: YAGEO; Manufacturer Part Number: CC1206JRX7R9BB333
footprint CAP-1206 (1206 (3216M) Capacitor)
pins: 1, 2

## CC1206JRX7R9BB472
designator C?  Capacitance: 4.7nF  (hidden comment: *)
Capacitor, Ceramic (MLCC), 4.7nF, ±5%, 50V, X7R, ±5%, SMD 1206; Manufacturer: YAGEO; Manufacturer Part Number: CC1206JRX7R9BB472
footprint CAP-1206 (1206 (3216M) Capacitor)
pins: 1, 2

## CC1206JRX7R9BB473
designator C?  Capacitance: 47nF  (hidden comment: *)
Capacitor, Ceramic (MLCC), 47nF, ±5%, 50V, X7R, ±5%, SMD 1206; Manufacturer: YAGEO; Manufacturer Part Number: CC1206JRX7R9BB473
footprint CAP-1206 (1206 (3216M) Capacitor)
pins: 1, 2

## CC1206JRX7R9BB563
designator C?  Capacitance: 56nF  (hidden comment: *)
Capacitor, Ceramic (MLCC), 56nF, ±5%, 50V, X7R, ±5%, SMD 1206; Manufacturer: YAGEO; Manufacturer Part Number: CC1206JRX7R9BB563
footprint CAP-1206 (1206 (3216M) Capacitor)
pins: 1, 2

## CC1206JRX7R9BB682
designator C?  Capacitance: 6.8nF  (hidden comment: *)
Capacitor, Ceramic (MLCC), 6.8nF, ±5%, 50V, X7R, ±5%, SMD 1206; Manufacturer: YAGEO; Manufacturer Part Number: CC1206JRX7R9BB682
footprint CAP-1206 (1206 (3216M) Capacitor)
pins: 1, 2

## CC1206JRX7R9BB683
designator C?  Capacitance: 68nF  (hidden comment: *)
Capacitor, Ceramic (MLCC), 68nF, ±5%, 50V, X7R, ±5%, SMD 1206; Manufacturer: YAGEO; Manufacturer Part Number: CC1206JRX7R9BB683
footprint CAP-1206 (1206 (3216M) Capacitor)
pins: 1, 2

## CC1206JRX7RABB102
designator C?  Capacitance: 1nF  (hidden comment: *)
Capacitor, Ceramic (MLCC), 1nF, ±5%, 200V, X7R, ±5%, SMD 1206; Manufacturer: YAGEO; Manufacturer Part Number: CC1206JRX7RABB102
footprint CAP-1206 (1206 (3216M) Capacitor)
pins: 1, 2

## CC1206JRX7RABB103
designator C?  Capacitance: 10nF  (hidden comment: *)
Capacitor, Ceramic (MLCC), 10nF, ±5%, 200V, X7R, ±5%, SMD 1206; Manufacturer: YAGEO; Manufacturer Part Number: CC1206JRX7RABB103
footprint CAP-1206 (1206 (3216M) Capacitor)
pins: 1, 2

## CC1206JRX7RABB153
designator C?  Capacitance: 15nF  (hidden comment: *)
Capacitor, Ceramic (MLCC), 15nF, ±5%, 200V, X7R, ±5%, SMD 1206; Manufacturer: YAGEO; Manufacturer Part Number: CC1206JRX7RABB153
footprint CAP-1206 (1206 (3216M) Capacitor)
pins: 1, 2

## CC1206JRX7RABB222
designator C?  Capacitance: 2.2nF  (hidden comment: *)
Capacitor, Ceramic (MLCC), 2.2nF, ±5%, 200V, X7R, ±5%, SMD 1206; Manufacturer: YAGEO; Manufacturer Part Number: CC1206JRX7RABB222
footprint CAP-1206 (1206 (3216M) Capacitor)
pins: 1, 2

## CC1206JRX7RYBB103
designator C?  Capacitance: 10nF  (hidden comment: *)
Capacitor, Ceramic (MLCC), 10nF, ±5%, 250V, X7R, ±5%, SMD 1206; Manufacturer: YAGEO; Manufacturer Part Number: CC1206JRX7RYBB103
footprint CAP-1206 (1206 (3216M) Capacitor)
pins: 1, 2

## CC1206KKX5R5BB226
designator C?  Capacitance: 22uF  (hidden comment: *)
Capacitor, Ceramic (MLCC), 22uF, ±10%, 6.3V, X5R, ±10%, SMD 1206; Manufacturer: YAGEO; Manufacturer Part Number: CC1206KKX5R5BB226
footprint CAP-1206 (1206 (3216M) Capacitor)
pins: 1, 2

## CC1206KKX5R6BB106
designator C?  Capacitance: 10uF  (hidden comment: *)
Capacitor, Ceramic (MLCC), 10uF, ±10%, 10V, X5R, ±10%, SMD 1206; Manufacturer: YAGEO; Manufacturer Part Number: CC1206KKX5R6BB106
footprint CAP-1206 (1206 (3216M) Capacitor)
pins: 1, 2

## CC1206KKX5R6BB226
designator C?  Capacitance: 22uF  (hidden comment: *)
Capacitor, Ceramic (MLCC), 22uF, ±10%, 10V, X5R, ±10%, SMD 1206; Manufacturer: YAGEO; Manufacturer Part Number: CC1206KKX5R6BB226
footprint CAP-1206 (1206 (3216M) Capacitor)
pins: 1, 2

## CC1206KKX5R7BB106
designator C?  Capacitance: 10uF  (hidden comment: *)
Capacitor, Ceramic (MLCC), 10uF, ±10%, 16V, X5R, ±10%, SMD 1206; Manufacturer: YAGEO; Manufacturer Part Number: CC1206KKX5R7BB106
footprint CAP-1206 (1206 (3216M) Capacitor)
pins: 1, 2

## CC1206KKX5R7BB225
designator C?  Capacitance: 2.2uF  (hidden comment: *)
Capacitor, Ceramic (MLCC), 2.2uF, ±10%, 16V, X5R, ±10%, SMD 1206; Manufacturer: YAGEO; Manufacturer Part Number: CC1206KKX5R7BB225
footprint CAP-1206 (1206 (3216M) Capacitor)
pins: 1, 2

## CC1206KKX5R8BB106
designator C?  Capacitance: 10uF  (hidden comment: *)
Capacitor, Ceramic (MLCC), 10uF, ±10%, 25V, X5R, ±10%, SMD 1206; Manufacturer: YAGEO; Manufacturer Part Number: CC1206KKX5R8BB106
footprint CAP-1206 (1206 (3216M) Capacitor)
pins: 1, 2

## CC1206KKX5R8BB225
designator C?  Capacitance: 2.2uF  (hidden comment: *)
Capacitor, Ceramic (MLCC), 2.2uF, ±10%, 25V, X5R, ±10%, SMD 1206; Manufacturer: YAGEO; Manufacturer Part Number: CC1206KKX5R8BB225
footprint CAP-1206 (1206 (3216M) Capacitor)
pins: 1, 2

## CC1206KKX5R8BB226
designator C?  Capacitance: 22uF  (hidden comment: *)
Capacitor, Ceramic (MLCC), 22uF, ±10%, 25V, X5R, ±10%, SMD 1206; Manufacturer: YAGEO; Manufacturer Part Number: CC1206KKX5R8BB226
footprint CAP-1206 (1206 (3216M) Capacitor)
pins: 1, 2

## CC1206KKX5R8BB475
designator C?  Capacitance: 4.7uF  (hidden comment: *)
Capacitor, Ceramic (MLCC), 4.7uF, ±10%, 25V, X5R, ±10%, SMD 1206; Manufacturer: YAGEO; Manufacturer Part Number: CC1206KKX5R8BB475
footprint CAP-1206 (1206 (3216M) Capacitor)
pins: 1, 2

## CC1206KKX5R9BB106
designator C?  Capacitance: 10uF  (hidden comment: *)
Capacitor, Ceramic (MLCC), 10uF, ±10%, 50V, X5R, ±10%, SMD 1206; Manufacturer: YAGEO; Manufacturer Part Number: CC1206KKX5R9BB106
footprint CAP-1206 (1206 (3216M) Capacitor)
pins: 1, 2

## CC1206KKX5R9BB225
designator C?  Capacitance: 2.2uF  (hidden comment: *)
Capacitor, Ceramic (MLCC), 2.2uF, ±10%, 50V, X5R, ±10%, SMD 1206; Manufacturer: YAGEO; Manufacturer Part Number: CC1206KKX5R9BB225
footprint CAP-1206 (1206 (3216M) Capacitor)
pins: 1, 2

## CC1206KKX7R0BB104
designator C?  Capacitance: 100nF  (hidden comment: *)
Capacitor, Ceramic (MLCC), 100nF, ±10%, 100V, X7R, ±10%, SMD 1206; Manufacturer: YAGEO; Manufacturer Part Number: CC1206KKX7R0BB104
footprint CAP-1206 (1206 (3216M) Capacitor)
pins: 1, 2

## CC1206KKX7R0BB105
designator C?  Capacitance: 1uF  (hidden comment: *)
Capacitor, Ceramic (MLCC), 1uF, ±10%, 100V, X7R, ±10%, SMD 1206; Manufacturer: YAGEO; Manufacturer Part Number: CC1206KKX7R0BB105
footprint CAP-1206 (1206 (3216M) Capacitor)
pins: 1, 2

## CC1206KKX7R0BB224
designator C?  Capacitance: 220nF  (hidden comment: *)
Capacitor, Ceramic (MLCC), 220nF, ±10%, 100V, X7R, ±10%, SMD 1206; Manufacturer: YAGEO; Manufacturer Part Number: CC1206KKX7R0BB224
footprint CAP-1206 (1206 (3216M) Capacitor)
pins: 1, 2

## CC1206KKX7R0BB474
designator C?  Capacitance: 470nF  (hidden comment: *)
Capacitor, Ceramic (MLCC), 470nF, ±10%, 100V, X7R, ±10%, SMD 1206; Manufacturer: YAGEO; Manufacturer Part Number: CC1206KKX7R0BB474
footprint CAP-1206 (1206 (3216M) Capacitor)
pins: 1, 2

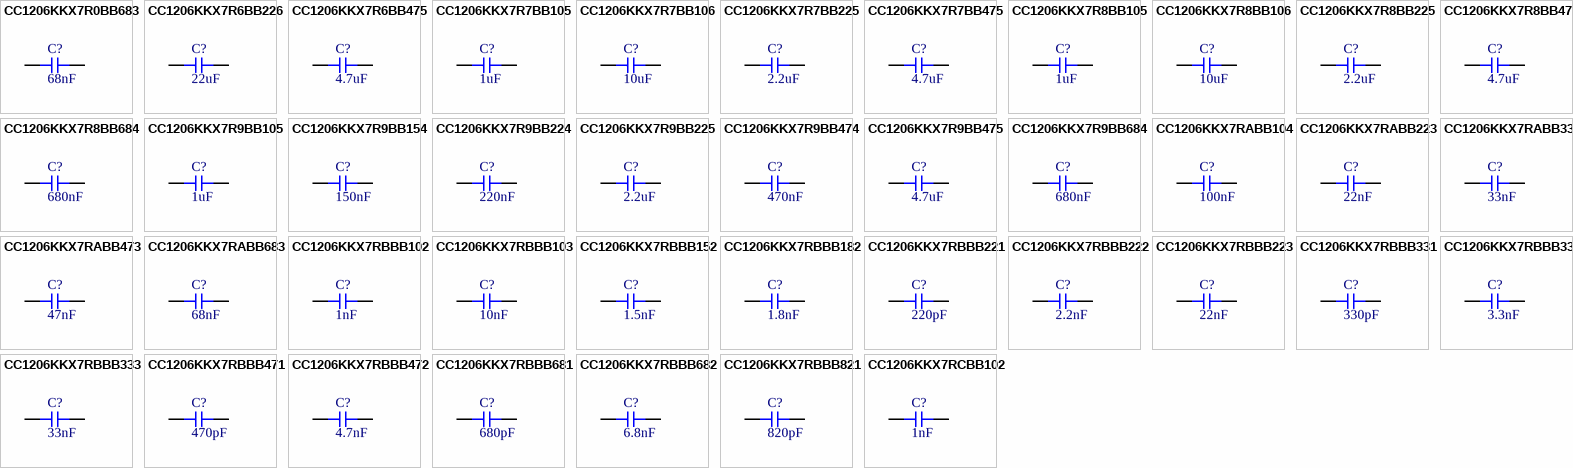
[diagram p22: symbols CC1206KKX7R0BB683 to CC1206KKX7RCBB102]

## CC1206KKX7R0BB683
designator C?  Capacitance: 68nF  (hidden comment: *)
Capacitor, Ceramic (MLCC), 68nF, ±10%, 100V, X7R, ±10%, SMD 1206; Manufacturer: YAGEO; Manufacturer Part Number: CC1206KKX7R0BB683
footprint CAP-1206 (1206 (3216M) Capacitor)
pins: 1, 2

## CC1206KKX7R6BB226
designator C?  Capacitance: 22uF  (hidden comment: *)
Capacitor, Ceramic (MLCC), 22uF, ±10%, 10V, X7R, ±10%, SMD 1206; Manufacturer: YAGEO; Manufacturer Part Number: CC1206KKX7R6BB226
footprint CAP-1206 (1206 (3216M) Capacitor)
pins: 1, 2

## CC1206KKX7R6BB475
designator C?  Capacitance: 4.7uF  (hidden comment: *)
Capacitor, Ceramic (MLCC), 4.7uF, ±10%, 10V, X7R, ±10%, SMD 1206; Manufacturer: YAGEO; Manufacturer Part Number: CC1206KKX7R6BB475
footprint CAP-1206 (1206 (3216M) Capacitor)
pins: 1, 2

## CC1206KKX7R7BB105
designator C?  Capacitance: 1uF  (hidden comment: *)
Capacitor, Ceramic (MLCC), 1uF, ±10%, 16V, X7R, ±10%, SMD 1206; Manufacturer: YAGEO; Manufacturer Part Number: CC1206KKX7R7BB105
footprint CAP-1206 (1206 (3216M) Capacitor)
pins: 1, 2

## CC1206KKX7R7BB106
designator C?  Capacitance: 10uF  (hidden comment: *)
Capacitor, Ceramic (MLCC), 10uF, ±10%, 16V, X7R, ±10%, SMD 1206; Manufacturer: YAGEO; Manufacturer Part Number: CC1206KKX7R7BB106
footprint CAP-1206 (1206 (3216M) Capacitor)
pins: 1, 2

## CC1206KKX7R7BB225
designator C?  Capacitance: 2.2uF  (hidden comment: *)
Capacitor, Ceramic (MLCC), 2.2uF, ±10%, 16V, X7R, ±10%, SMD 1206; Manufacturer: YAGEO; Manufacturer Part Number: CC1206KKX7R7BB225
footprint CAP-1206 (1206 (3216M) Capacitor)
pins: 1, 2

## CC1206KKX7R7BB475
designator C?  Capacitance: 4.7uF  (hidden comment: *)
Capacitor, Ceramic (MLCC), 4.7uF, ±10%, 16V, X7R, ±10%, SMD 1206; Manufacturer: YAGEO; Manufacturer Part Number: CC1206KKX7R7BB475
footprint CAP-1206 (1206 (3216M) Capacitor)
pins: 1, 2

## CC1206KKX7R8BB105
designator C?  Capacitance: 1uF  (hidden comment: *)
Capacitor, Ceramic (MLCC), 1uF, ±10%, 25V, X7R, ±10%, SMD 1206; Manufacturer: YAGEO; Manufacturer Part Number: CC1206KKX7R8BB105
footprint CAP-1206 (1206 (3216M) Capacitor)
pins: 1, 2

## CC1206KKX7R8BB106
designator C?  Capacitance: 10uF  (hidden comment: *)
Capacitor, Ceramic (MLCC), 10uF, ±10%, 25V, X7R, ±10%, SMD 1206; Manufacturer: YAGEO; Manufacturer Part Number: CC1206KKX7R8BB106
footprint CAP-1206 (1206 (3216M) Capacitor)
pins: 1, 2

## CC1206KKX7R8BB225
designator C?  Capacitance: 2.2uF  (hidden comment: *)
Capacitor, Ceramic (MLCC), 2.2uF, ±10%, 25V, X7R, ±10%, SMD 1206; Manufacturer: YAGEO; Manufacturer Part Number: CC1206KKX7R8BB225
footprint CAP-1206 (1206 (3216M) Capacitor)
pins: 1, 2

## CC1206KKX7R8BB475
designator C?  Capacitance: 4.7uF  (hidden comment: *)
Capacitor, Ceramic (MLCC), 4.7uF, ±10%, 25V, X7R, ±10%, SMD 1206; Manufacturer: YAGEO; Manufacturer Part Number: CC1206KKX7R8BB475
footprint CAP-1206 (1206 (3216M) Capacitor)
pins: 1, 2

## CC1206KKX7R8BB684
designator C?  Capacitance: 680nF  (hidden comment: *)
Capacitor, Ceramic (MLCC), 680nF, ±10%, 25V, X7R, ±10%, SMD 1206; Manufacturer: YAGEO; Manufacturer Part Number: CC1206KKX7R8BB684
footprint CAP-1206 (1206 (3216M) Capacitor)
pins: 1, 2

## CC1206KKX7R9BB105
designator C?  Capacitance: 1uF  (hidden comment: *)
Capacitor, Ceramic (MLCC), 1uF, ±10%, 50V, X7R, ±10%, SMD 1206; Manufacturer: YAGEO; Manufacturer Part Number: CC1206KKX7R9BB105
footprint CAP-1206 (1206 (3216M) Capacitor)
pins: 1, 2

## CC1206KKX7R9BB154
designator C?  Capacitance: 150nF  (hidden comment: *)
Capacitor, Ceramic (MLCC), 150nF, ±10%, 50V, X7R, ±10%, SMD 1206; Manufacturer: YAGEO; Manufacturer Part Number: CC1206KKX7R9BB154
footprint CAP-1206 (1206 (3216M) Capacitor)
pins: 1, 2

## CC1206KKX7R9BB224
designator C?  Capacitance: 220nF  (hidden comment: *)
Capacitor, Ceramic (MLCC), 220nF, ±10%, 50V, X7R, ±10%, SMD 1206; Manufacturer: YAGEO; Manufacturer Part Number: CC1206KKX7R9BB224
footprint CAP-1206 (1206 (3216M) Capacitor)
pins: 1, 2

## CC1206KKX7R9BB225
designator C?  Capacitance: 2.2uF  (hidden comment: *)
Capacitor, Ceramic (MLCC), 2.2uF, ±10%, 50V, X7R, ±10%, SMD 1206; Manufacturer: YAGEO; Manufacturer Part Number: CC1206KKX7R9BB225
footprint CAP-1206 (1206 (3216M) Capacitor)
pins: 1, 2

## CC1206KKX7R9BB474
designator C?  Capacitance: 470nF  (hidden comment: *)
Capacitor, Ceramic (MLCC), 470nF, ±10%, 50V, X7R, ±10%, SMD 1206; Manufacturer: YAGEO; Manufacturer Part Number: CC1206KKX7R9BB474
footprint CAP-1206 (1206 (3216M) Capacitor)
pins: 1, 2

## CC1206KKX7R9BB475
designator C?  Capacitance: 4.7uF  (hidden comment: *)
Capacitor, Ceramic (MLCC), 4.7uF, ±10%, 50V, X7R, ±10%, SMD 1206; Manufacturer: YAGEO; Manufacturer Part Number: CC1206KKX7R9BB475
footprint CAP-1206 (1206 (3216M) Capacitor)
pins: 1, 2

## CC1206KKX7R9BB684
designator C?  Capacitance: 680nF  (hidden comment: *)
Capacitor, Ceramic (MLCC), 680nF, ±10%, 50V, X7R, ±10%, SMD 1206; Manufacturer: YAGEO; Manufacturer Part Number: CC1206KKX7R9BB684
footprint CAP-1206 (1206 (3216M) Capacitor)
pins: 1, 2

## CC1206KKX7RABB104
designator C?  Capacitance: 100nF  (hidden comment: *)
Capacitor, Ceramic (MLCC), 100nF, ±10%, 200V, X7R, ±10%, SMD 1206; Manufacturer: YAGEO; Manufacturer Part Number: CC1206KKX7RABB104
footprint CAP-1206 (1206 (3216M) Capacitor)
pins: 1, 2

## CC1206KKX7RABB223
designator C?  Capacitance: 22nF  (hidden comment: *)
Capacitor, Ceramic (MLCC), 22nF, ±10%, 200V, X7R, ±10%, SMD 1206; Manufacturer: YAGEO; Manufacturer Part Number: CC1206KKX7RABB223
footprint CAP-1206 (1206 (3216M) Capacitor)
pins: 1, 2

## CC1206KKX7RABB333
designator C?  Capacitance: 33nF  (hidden comment: *)
Capacitor, Ceramic (MLCC), 33nF, ±10%, 200V, X7R, ±10%, SMD 1206; Manufacturer: YAGEO; Manufacturer Part Number: CC1206KKX7RABB333
footprint CAP-1206 (1206 (3216M) Capacitor)
pins: 1, 2

## CC1206KKX7RABB473
designator C?  Capacitance: 47nF  (hidden comment: *)
Capacitor, Ceramic (MLCC), 47nF, ±10%, 200V, X7R, ±10%, SMD 1206; Manufacturer: YAGEO; Manufacturer Part Number: CC1206KKX7RABB473
footprint CAP-1206 (1206 (3216M) Capacitor)
pins: 1, 2

## CC1206KKX7RABB683
designator C?  Capacitance: 68nF  (hidden comment: *)
Capacitor, Ceramic (MLCC), 68nF, ±10%, 200V, X7R, ±10%, SMD 1206; Manufacturer: YAGEO; Manufacturer Part Number: CC1206KKX7RABB683
footprint CAP-1206 (1206 (3216M) Capacitor)
pins: 1, 2

## CC1206KKX7RBBB102
designator C?  Capacitance: 1nF  (hidden comment: *)
Capacitor, Ceramic (MLCC), 1nF, ±10%, 500V, X7R, ±10%, SMD 1206; Manufacturer: YAGEO; Manufacturer Part Number: CC1206KKX7RBBB102
footprint CAP-1206 (1206 (3216M) Capacitor)
pins: 1, 2

## CC1206KKX7RBBB103
designator C?  Capacitance: 10nF  (hidden comment: *)
Capacitor, Ceramic (MLCC), 10nF, ±10%, 500V, X7R, ±10%, SMD 1206; Manufacturer: YAGEO; Manufacturer Part Number: CC1206KKX7RBBB103
footprint CAP-1206 (1206 (3216M) Capacitor)
pins: 1, 2

## CC1206KKX7RBBB152
designator C?  Capacitance: 1.5nF  (hidden comment: *)
Capacitor, Ceramic (MLCC), 1.5nF, ±10%, 500V, X7R, ±10%, SMD 1206; Manufacturer: YAGEO; Manufacturer Part Number: CC1206KKX7RBBB152
footprint CAP-1206 (1206 (3216M) Capacitor)
pins: 1, 2

## CC1206KKX7RBBB182
designator C?  Capacitance: 1.8nF  (hidden comment: *)
Capacitor, Ceramic (MLCC), 1.8nF, ±10%, 500V, X7R, ±10%, SMD 1206; Manufacturer: YAGEO; Manufacturer Part Number: CC1206KKX7RBBB182
footprint CAP-1206 (1206 (3216M) Capacitor)
pins: 1, 2

## CC1206KKX7RBBB221
designator C?  Capacitance: 220pF  (hidden comment: *)
Capacitor, Ceramic (MLCC), 220pF, ±10%, 500V, X7R, ±10%, SMD 1206; Manufacturer: YAGEO; Manufacturer Part Number: CC1206KKX7RBBB221
footprint CAP-1206 (1206 (3216M) Capacitor)
pins: 1, 2

## CC1206KKX7RBBB222
designator C?  Capacitance: 2.2nF  (hidden comment: *)
Capacitor, Ceramic (MLCC), 2.2nF, ±10%, 500V, X7R, ±10%, SMD 1206; Manufacturer: YAGEO; Manufacturer Part Number: CC1206KKX7RBBB222
footprint CAP-1206 (1206 (3216M) Capacitor)
pins: 1, 2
